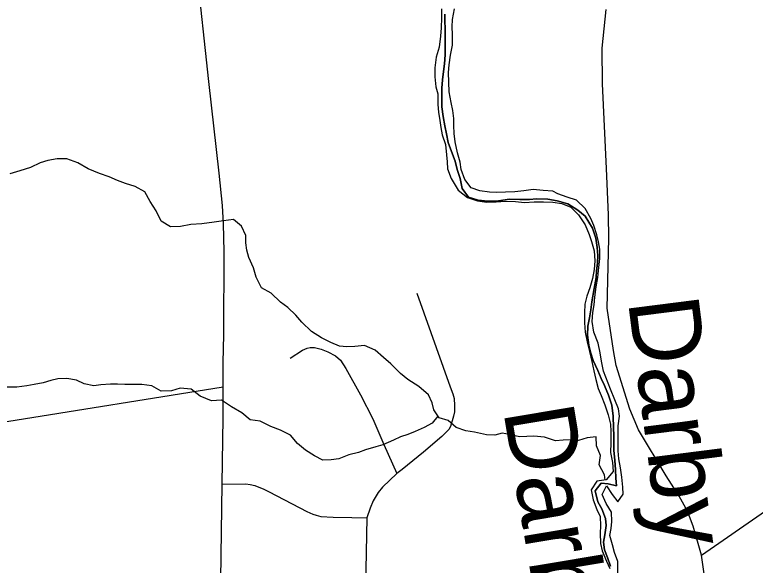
# Model space of a CAD drawing. Extents: x 114843 to 284848, y 317643 to 566895.
# Drawn here: x 131240 to 136492, y 408567 to 412474 of the extents above; entities that cross this region are included whole.
import ezdxf

# ---------------------------------------------------------------- set-up
doc = ezdxf.new("R2010")
doc.units = 0
for name, color, linetype in [('GM_X_County', 7, 'Continuous'), ('GM_X_County_Road', 7, 'Continuous'), ('GM_X_Major_River', 7, 'Continuous'), ('GM_X_Major_River_Text', 7, 'Continuous'), ('GM_X_Minor_River', 7, 'Continuous'), ('GM_X_Township', 7, 'Continuous'), ('GM_X_Township_Road', 7, 'Continuous')]:
    doc.layers.add(name, color=color, linetype=linetype)

msp = doc.modelspace()

# ---------------------------------------------------------------- linework, layer by layer
at = {"layer": 'GM_X_County'}
for points in [[(134290.9, 412478.4), (134290.7, 412428.3), (134292.5, 412376), (134294.2, 412305.8), (134293.7, 412189.3), (134287.4, 412127.1), (134281.2, 412070.9), (134274.9, 412012.8), (134268.6, 411952.6), (134268.3, 411874.3), (134270.1, 411820.1), (134279.9, 411751.8), (134291.6, 411685.5), (134301.5, 411629.3), (134315.2, 411569), (134339.1, 411504.7), (134362.9, 411434.3), (134378.7, 411376.1), (134400.6, 411311.8), (134414.3, 411241.5), (134458.7, 411179.7), (134527.2, 411158.2), (134594.8, 411151.4), (134671.7, 411154), (134749.4, 411166.1), (134823.7, 411163.8), (134892, 411163.6), (134942.2, 411167.4), (135020.5, 411165.1), (135088.8, 411154.9), (135163, 411132.6), (135233.2, 411088.1), (135285.2, 411043.8), (135339, 410959.3), (135360.8, 410889), (135370.6, 410822.7), (135376.3, 410766.7), (135374.5, 410710.6), (135366.3, 410656.6), (135363.4, 410610.1), (135351, 410531.2), (135334.4, 410437.2), (135326.1, 410381), (135316.3, 410323.1), (135306, 410264.9), (135303.8, 410200.7), (135311.5, 410130.4), (135327.3, 410072.1), (135343.2, 410019.9), (135377, 409949.5), (135400.9, 409893.2), (135422.8, 409843), (135452.6, 409774.6), (135474.4, 409702.3), (135484.2, 409625.9), (135487.8, 409543.6), (135489.6, 409487.4), (135489.2, 409383), (135496.9, 409310.8), (135500.7, 409246.5), (135504.4, 409184.3), (135508.2, 409130.1), (135450, 409144.3), (135399.8, 409150.5), (135357.4, 409094.4), (135377.2, 409018.1), (135405.1, 408967.8), (135430.9, 408899.5), (135434.7, 408849.3), (135426.4, 408783), (135416.2, 408730.9), (135424, 408676.7), (135443.8, 408622.4), (135465.7, 408560.1)], [(135465.7, 408560.1), (135443.8, 408622.4), (135424, 408676.7), (135416.2, 408730.9), (135426.4, 408783), (135434.7, 408849.3), (135430.9, 408899.5), (135405.1, 408967.8), (135377.2, 409018.1), (135357.4, 409094.4), (135399.8, 409150.5), (135450, 409144.3), (135508.2, 409130.1), (135504.4, 409184.3), (135500.7, 409246.5), (135496.9, 409310.8), (135489.2, 409383), (135489.6, 409487.4), (135487.8, 409543.6), (135484.2, 409625.9), (135474.4, 409702.3), (135452.6, 409774.6), (135422.8, 409843), (135400.9, 409893.2), (135377, 409949.5), (135343.2, 410019.9), (135327.3, 410072.1), (135311.5, 410130.4), (135303.8, 410200.7), (135306, 410264.9), (135316.3, 410323.1), (135326.1, 410381), (135334.4, 410437.2), (135351, 410531.2), (135363.4, 410610.1), (135366.3, 410656.6), (135374.5, 410710.6), (135376.3, 410766.7), (135370.6, 410822.7), (135360.8, 410889), (135339, 410959.3), (135285.2, 411043.8), (135233.2, 411088.1), (135163, 411132.6), (135088.8, 411154.9), (135020.5, 411165.1), (134942.2, 411167.4), (134892, 411163.6), (134823.7, 411163.8), (134749.4, 411166.1), (134671.7, 411154), (134594.8, 411151.4), (134527.2, 411158.2), (134458.7, 411179.7), (134414.3, 411241.5), (134400.6, 411311.8), (134378.7, 411376.1), (134362.9, 411434.3), (134339.1, 411504.7), (134315.2, 411569), (134301.5, 411629.3), (134291.6, 411685.5), (134279.9, 411751.8), (134270.1, 411820.1), (134268.3, 411874.3), (134268.6, 411952.6), (134274.9, 412012.8), (134281.2, 412070.9), (134287.4, 412127.1), (134293.7, 412189.3), (134294.2, 412305.8), (134292.5, 412376), (134290.7, 412428.3), (134290.9, 412478.4)]]:
    msp.add_lwpolyline(points, dxfattribs=at)
at = {"layer": 'GM_X_County_Road'}
for points in [[(132717.5, 409834.2), (132718.4, 410006), (132722.3, 410202.7), (132725.9, 410793), (132721.1, 410989.7), (132712.8, 411120.6), (132689.9, 411349), (132616.3, 412000.7), (132441.4, 413631.5), (132364.8, 414316), (132265.8, 415229.2), (132191.7, 415940)], [(136452.5, 404684.6), (136402.2, 405320.3), (136312.7, 406254.7), (136235.1, 407213.2), (136202.9, 407973), (136132.3, 408489.3), (136112.4, 408639.1), (136052, 408844.9), (136011.1, 408951.7), (135954.1, 409058.4), (135862, 409202.3), (135664.2, 409527.6), (135604.3, 409674.4), (135506.2, 409984.3), (135487.8, 410092.5), (135442.7, 410391.2), (135454.9, 410886.8), (135452.3, 411055.3), (135437.1, 411382.2), (135408.9, 411983.9), (135406, 412236.7), (135435, 412511.6)], [(121204, 410214.5), (123655.4, 410009.5), (123986.9, 409984.2), (124348, 409951.1), (124675.3, 409925.8), (125265.5, 409875.8), (125580.6, 409845.4), (125707.5, 409828.9), (125984.7, 409800.2), (126292.7, 409764.6), (126962.3, 409694.8), (127229.9, 409662.5), (127674.2, 409615.4), (129146.6, 409691.3), (129647.4, 409342.4), (132717.5, 409834.2)], [(132711.4, 409141.7), (132717.8, 409612.5), (132717.5, 409834.2)], [(132697.2, 407713.5), (132702.8, 408464.9), (132711.4, 409141.7)]]:
    msp.add_lwpolyline(points, dxfattribs=at)
at = {"layer": 'GM_X_Major_River'}
for points in [[(134266, 412516), (134267.9, 412451.9), (134263.8, 412381.7), (134259.8, 412321.5), (134249.7, 412245.3), (134229.6, 412173.2), (134219.5, 412097), (134219.5, 412034.8), (134227.4, 411962.6), (134241.4, 411912.5), (134241.4, 411838.3), (134245.4, 411784.1), (134255.3, 411724), (134261.3, 411673.8), (134271.3, 411621.7), (134295.3, 411553.5), (134303.3, 411481.3), (134307.2, 411431.2), (134309.2, 411381), (134335.2, 411312.8), (134385.3, 411228.6)], [(135092.9, 411204.1), (135056.9, 411222.2), (134988.7, 411226.2), (134918.5, 411234.3), (134850.4, 411224.3), (134788.2, 411218.3), (134720.1, 411216.4), (134657.9, 411212.4), (134607.8, 411214.4), (134539.6, 411224.5), (134477.5, 411246.6), (134433.4, 411304.8), (134407.4, 411377), (134399.5, 411427.1), (134381.5, 411495.3), (134363.5, 411573.5), (134357.5, 411631.7), (134355.5, 411687.8), (134353.6, 411737.9), (134347.6, 411796.1), (134335.6, 411852.3), (134321.7, 411926.5), (134319.7, 411996.7), (134317.7, 412064.8), (134321.8, 412119), (134329.9, 412187.1), (134346, 412259.3), (134346, 412333.5), (134342, 412387.7), (134344.1, 412439.8), (134360.2, 412516)], [(134385.3, 411228.6), (134451.4, 411176.4), (134521.5, 411154.3), (134587.7, 411144.3), (134655.8, 411146.2), (134724, 411152.2), (134792.2, 411148.1), (134856.3, 411142.1), (134924.5, 411146.1), (134990.6, 411146), (135056.8, 411144), (135120.9, 411133.9), (135185.1, 411107.8), (135239.2, 411053.6), (135287.2, 410983.4), (135315.3, 410915.2), (135331.3, 410865.1), (135349.3, 410798.9), (135355.2, 410728.7), (135349.2, 410666.5), (135337.1, 410602.4), (135319, 410536.2), (135298.9, 410478.1), (135284.8, 410419.9), (135280.8, 410359.8), (135280.7, 410287.6), (135286.7, 410221.4), (135300.6, 410153.2), (135316.6, 410085.1), (135332.6, 410012.9), (135348.6, 409946.7), (135362.6, 409886.5), (135378.6, 409822.3), (135398.6, 409772.2), (135426.6, 409706), (135448.6, 409635.8), (135466.6, 409567.6), (135468.6, 409517.5), (135468.5, 409435.3), (135466.5, 409367.1), (135480.4, 409296.9), (135484.4, 409232.7), (135436.2, 409172.6), (135368.1, 409164.6), (135329.9, 409102.5), (135341.9, 409032.3), (135369.9, 408962.1), (135391.9, 408911.9), (135395.9, 408847.8), (135391.8, 408793.6), (135395.8, 408721.5), (135407.8, 408669.3), (135437.8, 408595.1), (135461.8, 408542.9)], [(135517.9, 408480.8), (135518, 408593), (135494, 408657.2), (135480, 408711.4), (135462, 408777.6), (135470, 408827.7), (135476.1, 408877.8), (135472.1, 408944), (135434.1, 409006.2), (135406.1, 409068.4), (135438.2, 409130.5), (135478.3, 409068.3), (135518.3, 409016.1), (135556.4, 409072.3), (135554.5, 409122.4), (135546.5, 409192.6), (135536.5, 409258.8), (135524.6, 409322.9), (135520.6, 409379.1), (135520.7, 409557.6), (135528.8, 409625.7), (135522.8, 409677.9), (135496.8, 409742.1), (135464.8, 409816.3), (135416.8, 409944.6), (135402.8, 410016.8), (135392.8, 410075), (135378.8, 410143.2), (135348.8, 410221.4), (135334.8, 410297.6), (135340.9, 410361.8), (135349, 410415.9), (135355, 410470), (135365.1, 410542.2), (135375.2, 410610.4), (135383.2, 410680.6), (135391.3, 410744.7), (135389.3, 410810.9), (135381.4, 410863), (135369.4, 410913.2), (135347.4, 410979.4), (135327.4, 411029.5), (135285.3, 411099.7), (135225.2, 411157.9), (135159.1, 411180), (135092.9, 411204.1)]]:
    msp.add_lwpolyline(points, dxfattribs=at)
at = {"layer": 'GM_X_Minor_River'}
for points in [[(135427.8, 409171.6), (135424.5, 409207.8), (135386.7, 409280.1), (135395, 409346.2), (135367.2, 409414.5), (135363.5, 409478.7), (135299.3, 409470.9), (135239.2, 409453), (135185.1, 409457.3), (135131, 409455.4), (135074.9, 409449.6), (134998.9, 409476), (134922.8, 409484.2), (134872.7, 409480.4), (134820.6, 409478.6), (134750.6, 409494.9), (134698.5, 409505.1), (134644.4, 409491.3), (134586.3, 409493.5), (134500.2, 409511.8), (134440.2, 409520), (134372.2, 409544.3), (134314.3, 409594.7), (134250.3, 409612.9), (134212.4, 409669.2), (134200.6, 409719.4), (134174.8, 409775.6), (134107, 409836), (134029, 409886.4), (133977.1, 409928.7), (133907.3, 409997.1), (133855.4, 410041.4), (133795.5, 410093.7), (133721.5, 410126.1), (133653.4, 410120.3), (133595.3, 410118.5), (133543.2, 410122.7), (133481.3, 410149), (133415.3, 410181.3), (133345.4, 410225.6), (133275.5, 410292), (133233.7, 410342.3), (133177.8, 410396.6), (133125.9, 410434.9), (133058, 410499.3), (132990.1, 410535.6), (132952.3, 410612), (132934.6, 410678.2), (132900.8, 410750.5), (132887, 410804.7), (132879.2, 410854.8), (132879.4, 410906.9), (132847.7, 410973.2), (132791.8, 411021.5), (132719.6, 411011.8), (132655.5, 411002), (132567.3, 410990.2), (132489.1, 410986.5), (132415, 410972.7), (132344.8, 410969), (132278.9, 411009.3), (132243.1, 411081.6), (132199.3, 411147.9), (132163.6, 411218.2), (132093.6, 411256.6), (132025.6, 411276.9), (131967.6, 411297.1), (131909.6, 411323.4), (131841.6, 411347.7), (131761.6, 411380), (131687.7, 411422.4), (131609.7, 411452.8), (131541.6, 411453), (131473.4, 411439.2), (131421.2, 411423.4), (131351, 411391.5), (131276.8, 411365.7), (131204.6, 411345.9)], [(134241.8, 409625.5), (134200, 409575), (134143.8, 409545.2), (134079.6, 409515.3), (134027.4, 409495.4), (133977.3, 409477.6), (133927.1, 409455.7), (133850.8, 409421.9), (133800.7, 409408), (133728.5, 409386.2), (133678.3, 409368.4), (133610.2, 409350.6), (133539.9, 409322.8), (133483.8, 409314.9), (133425.7, 409313.1), (133365.7, 409343.4), (133301.8, 409383.8), (133245.9, 409430.1), (133196.1, 409490.4), (133126.1, 409526.7), (133056.1, 409553), (132980.1, 409589.4), (132910.1, 409599.7), (132850.2, 409648), (132776.3, 409692.4), (132706.3, 409738.7), (132636.2, 409733), (132556.2, 409767.3), (132490.3, 409817.7), (132412.2, 409824), (132352, 409804.1), (132277.9, 409802.4), (132212, 409840.7), (132141.9, 409849), (132019.7, 409849.4), (131969.6, 409853.6), (131919.5, 409851.8), (131851.4, 409848), (131801.3, 409840.2), (131733.3, 409854.4), (131677.3, 409880.7), (131609.2, 409893), (131545.1, 409891.2), (131495, 409879.4), (131440.8, 409861.5), (131376.7, 409849.7), (131324.6, 409839.9), (131254.4, 409830.1), (131140.2, 409830.5)]]:
    msp.add_lwpolyline(points, dxfattribs=at)
at = {"layer": 'GM_X_Township'}
for points in [[(134290.9, 412478.4), (134290.7, 412428.3), (134292.5, 412376), (134294.2, 412305.8), (134293.7, 412189.3), (134287.4, 412127.1), (134281.2, 412070.9), (134274.9, 412012.8), (134268.6, 411952.6), (134268.3, 411874.3), (134270.1, 411820.1), (134279.9, 411751.8), (134291.6, 411685.5), (134301.5, 411629.3), (134315.2, 411569), (134339.1, 411504.7), (134362.9, 411434.3), (134378.7, 411376.1), (134400.6, 411311.8), (134414.3, 411241.5), (134458.7, 411179.7), (134527.2, 411158.2), (134594.8, 411151.4), (134671.7, 411154), (134749.4, 411166.1), (134823.7, 411163.8), (134892, 411163.6), (134942.2, 411167.4), (135020.5, 411165.1), (135088.8, 411154.9), (135163, 411132.6), (135233.2, 411088.1), (135285.2, 411043.8), (135339, 410959.3), (135360.8, 410889), (135370.6, 410822.7), (135376.3, 410766.7), (135374.5, 410710.6), (135366.3, 410656.6), (135363.4, 410610.1), (135351, 410531.2), (135334.4, 410437.2), (135326.1, 410381), (135316.3, 410323.1), (135306, 410264.9), (135303.8, 410200.7), (135311.5, 410130.4), (135327.3, 410072.1), (135343.2, 410019.9), (135377, 409949.5), (135400.9, 409893.2), (135422.8, 409843), (135452.6, 409774.6), (135474.4, 409702.3), (135484.2, 409625.9), (135487.8, 409543.6), (135489.6, 409487.4), (135489.2, 409383), (135496.9, 409310.8), (135500.7, 409246.5), (135504.4, 409184.3), (135508.2, 409130.1), (135450, 409144.3), (135399.8, 409150.5), (135357.4, 409094.4), (135377.2, 409018.1), (135405.1, 408967.8), (135430.9, 408899.5), (135434.7, 408849.3), (135426.4, 408783), (135416.2, 408730.9), (135424, 408676.7), (135443.8, 408622.4), (135465.7, 408560.1)], [(135465.7, 408560.1), (135443.8, 408622.4), (135424, 408676.7), (135416.2, 408730.9), (135426.4, 408783), (135434.7, 408849.3), (135430.9, 408899.5), (135405.1, 408967.8), (135377.2, 409018.1), (135357.4, 409094.4), (135399.8, 409150.5), (135450, 409144.3), (135508.2, 409130.1), (135504.4, 409184.3), (135500.7, 409246.5), (135496.9, 409310.8), (135489.2, 409383), (135489.6, 409487.4), (135487.8, 409543.6), (135484.2, 409625.9), (135474.4, 409702.3), (135452.6, 409774.6), (135422.8, 409843), (135400.9, 409893.2), (135377, 409949.5), (135343.2, 410019.9), (135327.3, 410072.1), (135311.5, 410130.4), (135303.8, 410200.7), (135306, 410264.9), (135316.3, 410323.1), (135326.1, 410381), (135334.4, 410437.2), (135351, 410531.2), (135363.4, 410610.1), (135366.3, 410656.6), (135374.5, 410710.6), (135376.3, 410766.7), (135370.6, 410822.7), (135360.8, 410889), (135339, 410959.3), (135285.2, 411043.8), (135233.2, 411088.1), (135163, 411132.6), (135088.8, 411154.9), (135020.5, 411165.1), (134942.2, 411167.4), (134892, 411163.6), (134823.7, 411163.8), (134749.4, 411166.1), (134671.7, 411154), (134594.8, 411151.4), (134527.2, 411158.2), (134458.7, 411179.7), (134414.3, 411241.5), (134400.6, 411311.8), (134378.7, 411376.1), (134362.9, 411434.3), (134339.1, 411504.7), (134315.2, 411569), (134301.5, 411629.3), (134291.6, 411685.5), (134279.9, 411751.8), (134270.1, 411820.1), (134268.3, 411874.3), (134268.6, 411952.6), (134274.9, 412012.8), (134281.2, 412070.9), (134287.4, 412127.1), (134293.7, 412189.3), (134294.2, 412305.8), (134292.5, 412376), (134290.7, 412428.3), (134290.9, 412478.4)]]:
    msp.add_lwpolyline(points, dxfattribs=at)
at = {"layer": 'GM_X_Township_Road'}
for points in [[(136112.4, 408639.1), (137018.4, 409266.9), (137572.6, 409651.1), (137817.7, 409824.2), (138020.2, 409959.6), (139374.3, 410832.3), (140589, 411660.3), (140812.7, 411811.8)], [(134091.5, 410498), (134329.4, 409832.6), (134348.2, 409784.4), (134356.4, 409751), (134360, 409701.2), (134359.6, 409656.5), (134352.4, 409624.2), (134332.1, 409551.1), (134319.3, 409529.5), (134269.4, 409480.1), (134138.4, 409369.6), (133988.8, 409246.8), (133949.7, 409217.6)], [(133193.5, 410036.9), (133282.2, 410094.3), (133313.6, 410107.5), (133335.2, 410112.7), (133365.4, 410113.6), (133414.3, 410100.3), (133461.8, 410081.3), (133515.2, 410053.7), (133550.5, 410023.7), (133587.6, 409963), (133693, 409776.6), (133780.5, 409606.7), (133858.6, 409423.1), (133949.7, 409217.6)], [(133949.7, 409217.6), (133848.1, 409121), (133818.9, 409083.9), (133802.6, 409060.2), (133781.3, 409023.2), (133761.3, 408972.2), (133737.4, 408903.8)], [(132711.4, 409141.7), (132878.4, 409144.3), (132909.7, 409140.8), (132943.5, 409133.9), (133006.9, 409107.2), (133045.6, 409088.8), (133312.1, 408948.7), (133354.3, 408929.7), (133378.5, 408921.5), (133411.1, 408912.9), (133497.8, 408907.5), (133631.4, 408907), (133737.4, 408903.8)], [(133737.4, 408903.8), (133728.6, 408413.4), (133731.3, 408292.9), (133751.5, 408211.4), (133805.3, 408070.4), (133820.4, 408020.5), (133835.6, 407955), (133840.3, 407738.5)]]:
    msp.add_lwpolyline(points, dxfattribs=at)

# ---------------------------------------------------------------- texts
at = {"layer": 'GM_X_Major_River_Text'}
for rotation, p in [(277.2434, (135589.2, 410444.3)), (279.5407, (134704.5, 409663.6))]:
    msp.add_text('Darby', height=499.95, rotation=rotation, dxfattribs=at).set_placement(p)

doc.saveas('drawing.dxf')
